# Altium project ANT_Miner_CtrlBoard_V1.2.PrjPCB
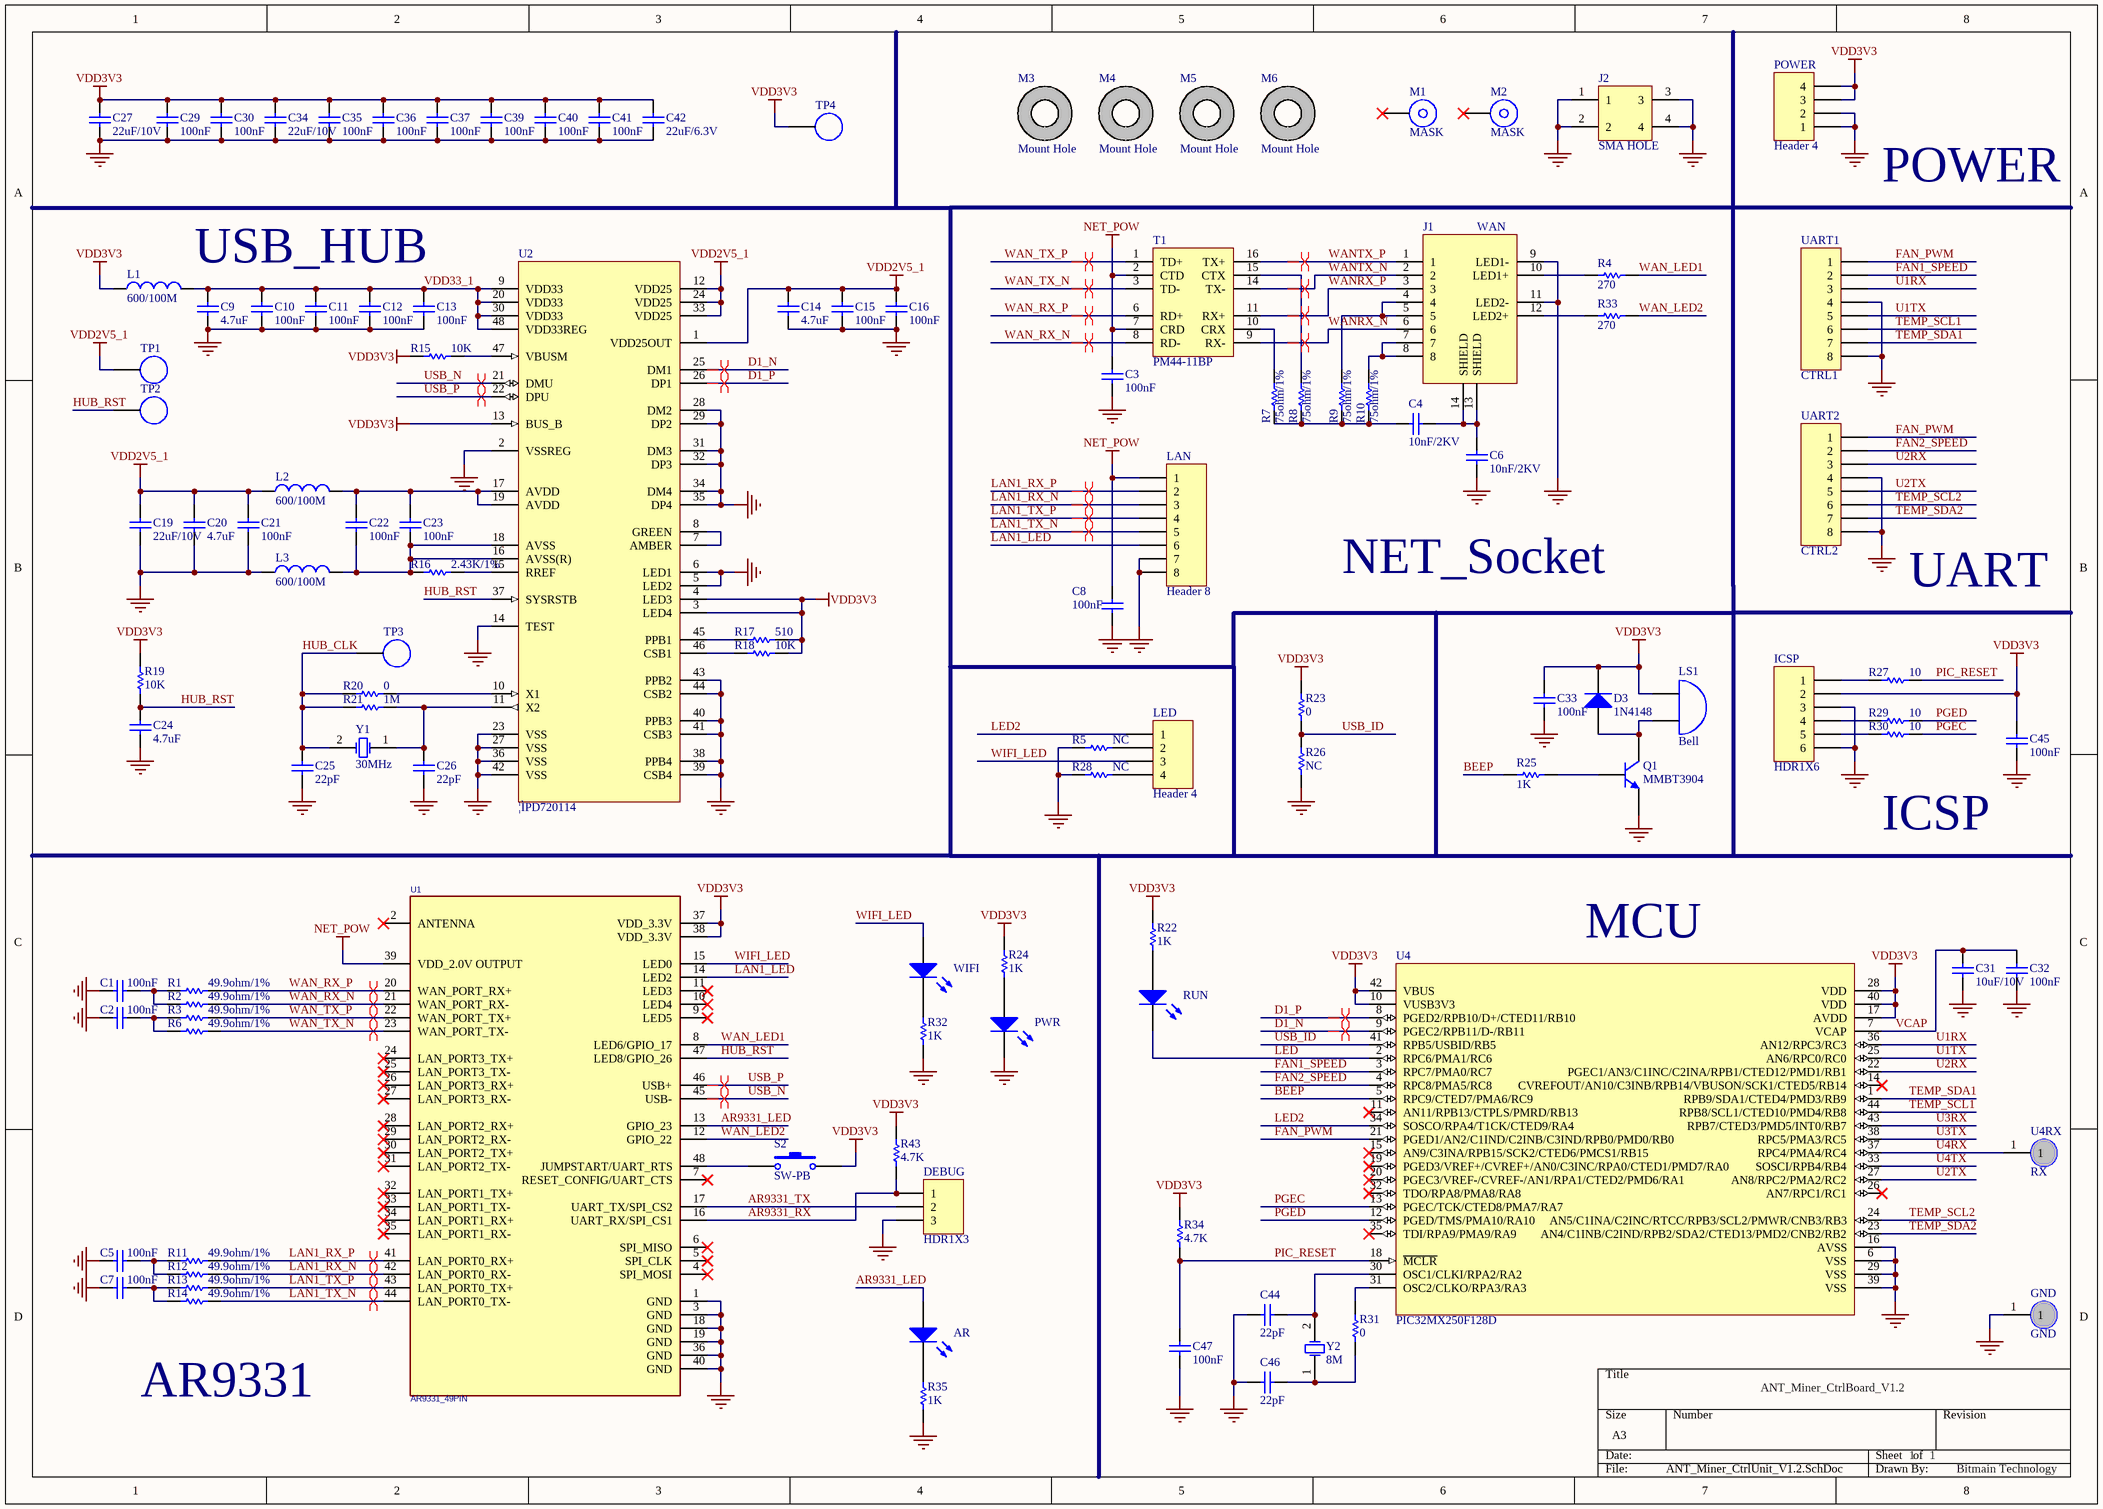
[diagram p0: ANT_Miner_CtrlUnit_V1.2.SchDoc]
1 sheet, 116 parts. Net scope: global (net labels, ports and power ports of the same name join across sheets).
Board file: ANT_Miner_CtrlBoard_V1.2.PcbDoc

## Sheet ANT_Miner_CtrlUnit_V1.2.SchDoc: ANT_Miner_CtrlBoard_V1.2
size A3; Date: 2013/11/29; DrawnBy: Bitmain Technology; SheetNumber: 1; SheetTotal: 1

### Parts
AR  Green  [LED0603(1608)]  (value not drawn)
C1  100nF  [CC0603(1608)]
C2  100nF  [CC0603(1608)]
C3  100nF  [CC0603(1608)]
C4  10nF/2KV  [1812]
C5  100nF  [CC0603(1608)]
C6  10nF/2KV  [1812]
C7  100nF  [CC0603(1608)]
C8  100nF  [CC0603(1608)]
C9  4.7uF  [CC0603(1608)]
C10  100nF  [CC0603(1608)]
C11  100nF  [CC0603(1608)]
C12  100nF  [CC0603(1608)]
C13  100nF  [CC0603(1608)]
C14  4.7uF  [CC0603(1608)]
C15  100nF  [CC0603(1608)]
C16  100nF  [CC0603(1608)]
C19  22uF/10V  [CC1210(3225)]
C20  4.7uF  [CC0603(1608)]
C21  100nF  [CC0603(1608)]
C22  100nF  [CC0603(1608)]
C23  100nF  [CC0603(1608)]
C24  4.7uF  [CC0603(1608)]
C25  22pF  [CC0603(1608)]
C26  22pF  [CC0603(1608)]
C27  22uF/10V  [CC1210(3225)]
C29  100nF  [CC0603(1608)]
C30  100nF  [CC0603(1608)]
C31  10uF/10V  [CC1210(3225)]
C32  100nF  [CC0603(1608)]
C33  100nF  [CC0603(1608)]
C34  22uF/10V  [CC1210(3225)]
C35  100nF  [CC0603(1608)]
C36  100nF  [CC0603(1608)]
C37  100nF  [CC0603(1608)]
C39  100nF  [CC0603(1608)]
C40  100nF  [CC0603(1608)]
C41  100nF  [CC0603(1608)]
C42  22uF/6.3V  [CC1210(3225)]
C44  22pF  [CC0603(1608)]
C45  100nF  [CC0603(1608)]
C46  22pF  [CC0603(1608)]
C47  100nF  [CC0603(1608)]
D3  1N4148  [DIODE0805]
DEBUG  HDR1X3  [HDR1X3]
GND  GND  [TP_DIP_1.5mm]
ICSP  HDR1X6  [HDR1X6]
J1  WAN  [RJ45_2LED_DIP]
J2  SMA HOLE  [SMA_HOLE]
L1  600/100M  [INDC1608L]
L2  600/100M  [INDC1608L]
L3  600/100M  [INDC1608L]
LAN  Header 8  [8Pin_180]
LED  Header 4  [4Pin_180]
LS1  Bell  [YR5025A]
M1  MASK  [MASK]
M2  MASK  [MASK]
M3  Mount Hole  [HOLE_3.2]
M4  Mount Hole  [HOLE_3.2]
M5  Mount Hole  [HOLE_3.2]
M6  Mount Hole  [HOLE_3.2]
POWER  Header 4  [4Pin_180]
PWR  Red  [LED0603(1608)]  (value not drawn)
Q1  MMBT3904  [SOT23_L]
R1  49.9ohm/1%  [RR0603(1608)]
R2  49.9ohm/1%  [RR0603(1608)]
R3  49.9ohm/1%  [RR0603(1608)]
R4  270  [RR0603(1608)]
R5  NC  [RR0603(1608)]
R6  49.9ohm/1%  [RR0603(1608)]
R7  75ohm/1%  [RR0603(1608)]
R8  75ohm/1%  [RR0603(1608)]
R9  75ohm/1%  [RR0603(1608)]
R10  75ohm/1%  [RR0603(1608)]
R11  49.9ohm/1%  [RR0603(1608)]
R12  49.9ohm/1%  [RR0603(1608)]
R13  49.9ohm/1%  [RR0603(1608)]
R14  49.9ohm/1%  [RR0603(1608)]
R15  10K  [RR0603(1608)]
R16  2.43K/1%  [RR0603(1608)]
R17  510  [RR0603(1608)]
R18  10K  [RR0603(1608)]
R19  10K  [RR0603(1608)]
R20  0  [RR0603(1608)]
R21  1M  [RR0603(1608)]
R22  1K  [RR0603(1608)]
R23  0  [RR0603(1608)]
R24  1K  [RR0603(1608)]
R25  1K  [RR0603(1608)]
R26  NC  [RR0603(1608)]
R27  10  [RR0603(1608)]
R28  NC  [RR0603(1608)]
R29  10  [RR0603(1608)]
R30  10  [RR0603(1608)]
R31  0  [RR0603(1608)]
R32  1K  [RR0603(1608)]
R33  270  [RR0603(1608)]
R34  4.7K  [RR0603(1608)]
R35  1K  [RR0603(1608)]
R43  4.7K  [RR0603(1608)]
RUN  Green  [LED0603(1608)]  (value not drawn)
S2  SW-PB  [SWITCH_3x4]
T1  PM44-11BP  [PM44-11BP]
TP1  TP  [TP2]  (value not drawn)
TP2  TP  [TP2]  (value not drawn)
TP3  TP  [TP2]  (value not drawn)
TP4  TP  [TP2]  (value not drawn)
U1  AR9331_49PIN  [AR9331_49PIN]
U2  ¦ÌPD720114  [TQFP48_L]
U4  PIC32MX250F128D  [TQFP44_L]
U4RX  RX  [TP_DIP_1.5mm]
UART1  CTRL1  [8Pin_180]
UART2  CTRL2  [8Pin_180]
WIFI  Green  [LED0603(1608)]  (value not drawn)
Y1  30MHz  [4SMX]
Y2  8M  [4SMX]

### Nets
GND: C1.2 C2.2 C3.2 C5.2 C6.2 C7.2 C8.2 C9.1 C10.1 C11.1 C12.1 C13.1 C14.1 C15.1 C16.1 C19.1 C20.1 C21.1 C24.1 C25.1 C26.1 C27.1 C29.1 C30.1 C31.1 C32.1 C33.1 C34.1 C35.1 C36.1 C37.1 C39.1 C40.1 C41.1 C42.1 C44.1 C45.1 C46.1 C47.1 DEBUG.3 GND.1 ICSP.3 ICSP.6 J1.9(LED1-) J1.11(LED2-) J2.1 J2.2 J2.3 J2.4 L3.1 LAN.7 LAN.8 POWER.1 POWER.2 PWR.2(K) Q1.2(E) R5.2 R26.1 R28.2 R32.1 R35.1 U1.1(GND) U1.3(GND) U1.18(GND) U1.19(GND) U1.36(GND) U1.40(GND) U2.2(VSSREG) U2.5(LED2) U2.6(LED1) U2.14(TEST) U2.23(VSS) U2.27(VSS) U2.28(DM2) U2.29(DP2) U2.31(DM3) U2.32(DP3) U2.34(DM4) U2.35(DP4) U2.36(VSS) U2.38(PPB4) U2.39(CSB4) U2.40(PPB3) U2.41(CSB3) U2.42(VSS) U2.43(PPB2) U2.44(CSB2) U4.6(VSS) U4.16(AVSS) U4.29(VSS) U4.39(VSS) UART1.4 UART1.8 UART2.4 UART2.8
NET_POW: C3.1 C8.1 LAN.1 T1.2(CTD) T1.7(CRD) U1.39(VDD_2.0V_OUTPUT)
VDD2V5_1: C14.2 C15.2 C16.2 C19.2 C20.2 C21.2 L2.1 TP1.1 U2.1(VDD25OUT) U2.12(VDD25) U2.24(VDD25) U2.33(VDD25)
VDD3V3: C27.2 C29.2 C30.2 C33.2 C34.2 C35.2 C36.2 C37.2 C39.2 C40.2 C41.2 C42.2 C45.2 D3.2(K) ICSP.2 L1.1 LS1.1(A) POWER.3 POWER.4 R15.1 R17.2 R18.2 R19.2 R22.2 R23.2 R24.2 R34.2 R43.2 S2.2 TP4.1 U1.37(VDD_3.3V) U1.38(VDD_3.3V) U2.3(LED4) U2.4(LED3) U2.13(BUS_B) U4.10(VUSB3V3) U4.17(AVDD) U4.28(VDD) U4.40(VDD) U4.42(VBUS)
AR9331_LED: AR.1(A) U1.13(GPIO_23)
AR9331_RX: DEBUG.1 R43.1 U1.16(UART_RX/SPI_CS1)
AR9331_TX: DEBUG.2 U1.17(UART_TX/SPI_CS2)
BEEP: R25.2 U4.5(RPC9/CTED7/PMA6/RC9)
D1_N: U2.25(DM1) U4.9(PGEC2/RPB11/D-/RB11)
D1_P: U2.26(DP1) U4.8(PGED2/RPB10/D+/CTED11/RB10)
FAN1_SPEED: U4.3(RPC7/PMA0/RC7) UART1.2
FAN2_SPEED: U4.4(RPC8/PMA5/RC8) UART2.2
FAN_PWM: U4.21(PGED1/AN2/C1IND/C2INB/C3IND/RPB0/PMD0/RB0) UART1.1 UART2.1
HUB_CLK: C25.2 R20.2 R21.2 TP3.1 Y1.2(OSC2)
HUB_RST: C24.2 R19.1 TP2.1 U1.47(LED8/GPIO_26) U2.37(SYSRSTB)
LAN1_LED: LAN.6 U1.14(LED2)
LAN1_RX_N: LAN.3 R12.2 U1.42(LAN_PORT0_RX-)
LAN1_RX_P: LAN.2 R11.2 U1.41(LAN_PORT0_RX+)
LAN1_TX_N: LAN.5 R14.2 U1.44(LAN_PORT0_TX-)
LAN1_TX_P: LAN.4 R13.2 U1.43(LAN_PORT0_TX+)
LED: RUN.2(K) U4.2(RPC6/PMA1/RC6)
LED2: LED.1 U4.34(SOSCO/RPA4/T1CK/CTED9/RA4)
PGEC: R30.1 U4.13(PGEC/TCK/CTED8/PMA7/RA7)
PGED: R29.1 U4.12(PGED/TMS/PMA10/RA10)
PIC_RESET: C47.2 R27.1 R34.1 U4.18(~{MCLR})
TEMP_SCL1: U4.44(RPB8/SCL1/CTED10/PMD4/RB8) UART1.6
TEMP_SCL2: U4.24(AN5/C1INA/C2INC/RTCC/RPB3/SCL2/PMWR/CNB3/RB3) UART2.6
TEMP_SDA1: U4.1(RPB9/SDA1/CTED4/PMD3/RB9) UART1.7
TEMP_SDA2: U4.23(AN4/C1INB/C2IND/RPB2/SDA2/CTED13/PMD2/CNB2/RB2) UART2.7
U1RX: U4.36(AN12/RPC3/RC3) UART1.3
U1TX: U4.25(AN6/RPC0/RC0) UART1.5
U2RX: U4.22(PGEC1/AN3/C1INC/C2INA/RPB1/CTED12/PMD1/RB1) UART2.3
U2TX: U4.27(AN8/RPC2/PMA2/RC2) UART2.5
U3RX: U4.43(RPB7/CTED3/PMD5/INT0/RB7)
U3TX: U4.38(RPC5/PMA3/RC5)
U4RX: U4.37(RPC4/PMA4/RC4) U4RX.1
U4TX: U4.33(SOSCI/RPB4/RB4)
USB_ID: R23.1 R26.2 U4.41(RPB5/USBID/RB5)
USB_N: U1.45(USB-) U2.21(DMU)
USB_P: U1.46(USB+) U2.22(DPU)
VCAP: C31.2 C32.2 U4.7(VCAP)
VDD33_1: C9.2 C10.2 C11.2 C12.2 C13.2 L1.2 U2.9(VDD33) U2.20(VDD33) U2.30(VDD33) U2.48(VDD33REG)
WAN_LED1: R4.1 U1.8(LED6/GPIO_17)
WAN_LED2: R33.1 U1.12(GPIO_22)
WAN_RX_N: R2.2 T1.8(RD-) U1.21(WAN_PORT_RX-)
WAN_RX_P: R1.2 T1.6(RD+) U1.20(WAN_PORT_RX+)
WAN_TX_N: R6.2 T1.3(TD-) U1.23(WAN_PORT_TX-)
WAN_TX_P: R3.2 T1.1(TD+) U1.22(WAN_PORT_TX+)
WANRX_N: J1.6 T1.9(RX-)
WANRX_P: J1.3 T1.11(RX+)
WANTX_N: J1.2 T1.14(TX-)
WANTX_P: J1.1 T1.16(TX+)
WIFI_LED: LED.3 U1.15(LED0) WIFI.1(A)
NetAR_2: AR.2(K) R35.2
NetC1_1: C1.1 R1.1 R2.1
NetC2_1: C2.1 R3.1 R6.1
NetC4_1: C4.1 C6.1 J1.13(SHIELD) J1.14(SHIELD)
NetC4_2: C4.2 R7.2 R8.2 R9.2 R10.2
NetC5_1: C5.1 R11.1 R12.1
NetC7_1: C7.1 R13.1 R14.1
NetC22_1: C22.1 C23.1 L3.2 R16.1 U2.16(AVSS(R)) U2.18(AVSS)
NetC22_2: C22.2 C23.2 L2.2 U2.17(AVDD) U2.19(AVDD)
NetC26_2: C26.2 R21.1 U2.11(X2) Y1.1(OSC1)
NetC44_2: C44.2 U4.30(OSC1/CLKI/RPA2/RA2) Y2.2(OSC2)
NetC46_2: C46.2 R31.1 Y2.1(OSC1)
NetD3_1: D3.1(A) LS1.2(B) Q1.3(C)
NetICSP_1: ICSP.1 R27.2
NetICSP_4: ICSP.4 R29.2
NetICSP_5: ICSP.5 R30.2
NetJ1_4: J1.4 J1.5 R9.1
NetJ1_7: J1.7 J1.8 R10.1
NetJ1_10: J1.10(LED1+) R4.2
NetJ1_12: J1.12(LED2+) R33.2
NetLED_2: LED.2 R5.1
NetLED_4: LED.4 R28.1
NetPWR_1: PWR.1(A) R24.1
NetQ1_1: Q1.1(B) R25.1
NetR7_1: R7.1 T1.10(CRX)
NetR8_1: R8.1 T1.15(CTX)
NetR15_2: R15.2 U2.47(VBUSM)
NetR16_2: R16.2 U2.15(RREF)
NetR17_1: R17.1 U2.45(PPB1)
NetR18_1: R18.1 U2.46(CSB1)
NetR20_1: R20.1 U2.10(X1)
NetR22_1: R22.1 RUN.1(A)
NetR31_2: R31.2 U4.31(OSC2/CLKO/RPA3/RA3)
NetR32_2: R32.2 WIFI.2(K)
NetS2_1: S2.1 U1.48(JUMPSTART/UART_RTS)
NetU2_7: U2.7(AMBER) U2.8(GREEN)

Not connected (* = marked no-connect by the designer): M1 1*; M2 1*; M3 0(PIN); M4 0(PIN); M5 0(PIN); M6 0(PIN); U1 2(ANTENNA)* 4(SPI_MOSI)* 5(SPI_CLK)* 6(SPI_MISO)* 7(RESET_CONFIG/UART_CTS)* 9(LED5)* 10(LED4)* 11(LED3)* 24(LAN_PORT3_TX+)* 25(LAN_PORT3_TX-)* 26(LAN_PORT3_RX+)* 27(LAN_PORT3_RX-)* 28(LAN_PORT2_RX+)* 29(LAN_PORT2_RX-)* 30(LAN_PORT2_TX+)* 31(LAN_PORT2_TX-)* 32(LAN_PORT1_TX+)* 33(LAN_PORT1_TX-)* 34(LAN_PORT1_RX+)* 35(LAN_PORT1_RX-)*; U4 11(AN11/RPB13/CTPLS/PMRD/RB13)* 14(CVREFOUT/AN10/C3INB/RPB14/VBUSON/SCK1/CTED5/RB14)* 15(AN9/C3INA/RPB15/SCK2/CTED6/PMCS1/RB15)* 19(PGED3/VREF+/CVREF+/AN0/C3INC/RPA0/CTED1/PMD7/RA0)* 20(PGEC3/VREF-/CVREF-/AN1/RPA1/CTED2/PMD6/RA1)* 26(AN7/RPC1/RC1)* 32(TDO/RPA8/PMA8/RA8)* 35(TDI/RPA9/PMA9/RA9)*

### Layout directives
differential pair: D1_N, D1_P, LAN1_RX_N, LAN1_RX_P, LAN1_TX_N, LAN1_TX_P, USB_N, USB_P, WAN_RX_N, WAN_RX_P, WAN_TX_N, WAN_TX_P, WANRX_N, WANRX_P, WANTX_N, WANTX_P

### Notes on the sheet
- POWER
- USB_HUB
- NET_Socket
- UART
- ICSP
- (near U4) MCU
- AR9331

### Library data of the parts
AR PWR RUN WIFI = LED0: Typical INFRARED GaAs LED
C1-C16 C19-C27 C29-C37 C39-C42 C44-C47 = Cap Semi: Capacitor (Semiconductor SIM Model)
D3 = Diode 1N4148: High Conductance Fast Diode
DEBUG = Header 3: Header, 3-Pin
GND U4RX = TP
ICSP = Header 6: Header, 6-Pin
J1 = RJ45-DIP: RJ45,DUAL LED,DIP
J2 = SMA_HOLE: SMA Socket Assembly Hole.
L1-L3 = Inductor: Code_IEC: 1005
LAN UART1 UART2 = Header 8: Header, 8-Pin
LED POWER = Header 4: Header, 4-Pin
LS1 = Bell: Electrical Bell
M3-M6 = M_Hole
Q1 = MMBT3904: NPN Switching Transistor
R1-R35 R43 = Res1: Resistor
S2 = SW-PB: Switch
TP1-TP4 = TP2
U2 = uPD720114
Y1 Y2 = XTAL: Crystal Oscillator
